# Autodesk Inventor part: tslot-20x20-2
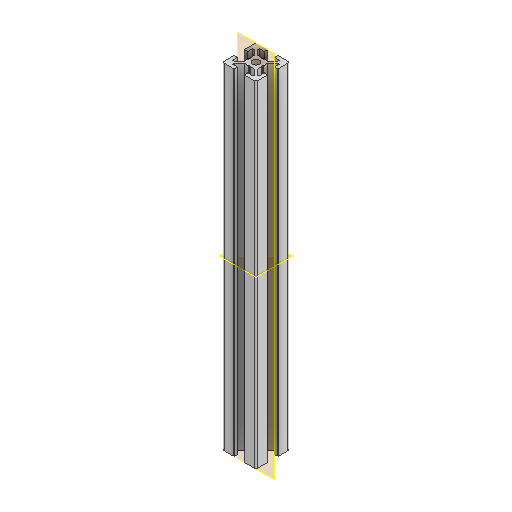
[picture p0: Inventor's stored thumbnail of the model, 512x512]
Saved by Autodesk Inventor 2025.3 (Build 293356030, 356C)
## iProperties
Created: 2025-03
Part Number: tslot-20x20-2
Material: Generico
Document SubType Name: Modeling
Designer: Ryzen5700u
Density: 1 g/cm^3
Appearance: Default
Author: Ryzen5700u
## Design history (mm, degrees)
feature "Base1"
sketch "Schizzo1"
  geometry: L1 (3.761, -16)-(4.7, -16) reference; L2 (3.761, -16)-(0.7, -12.939) reference; L3 (0.7, -12.939)-(0.7, -10.52) reference; L4 (0.4, -10)-(0.7, -10.52) reference; L5 (0.4, -10)-(0.7, -9.48) reference; L6 (0.7, -7.061)-(0.7, -9.48) reference; L7 (3.761, -4)-(0.7, -7.061) reference; L8 (3.761, -4)-(4.7, -4) reference; L9 (4.7, -4)-(4.7, -7) reference; L10 (4.7, -7)-(6.4, -7) reference; L11 (6.7, -6.7)-(6.7, -1) reference; L12 (5.7, 0)-(0, 0) reference; L13 (-0.3, -2)-(-0.3, -0.3) reference; L14 (2.7, -2)-(-0.3, -2) reference; L15 (2.7, -2.939)-(2.7, -2) reference; L16 (2.7, -2.939)-(-0.361, -6) reference; L17 (-0.361, -6)-(-2.78, -6) reference; L18 (-3.3, -6.3)-(-2.78, -6) reference; L19 (-3.3, -6.3)-(-3.82, -6) reference; L20 (-6.239, -6)-(-3.82, -6) reference; L21 (-9.3, -2.939)-(-6.239, -6) reference; L22 (-9.3, -2.939)-(-9.3, -2) reference; L23 (-9.3, -2)-(-6.3, -2) reference; L24 (-6.3, -2)-(-6.3, -0.3) reference; L25 (-12.3, 0)-(-6.6, 0) reference; L26 (-13.3, -6.7)-(-13.3, -1) reference; L27 (-11.3, -7)-(-13, -7) reference; L28 (-11.3, -4)-(-11.3, -7) reference; L29 (-10.361, -4)-(-11.3, -4) reference; L30 (-10.361, -4)-(-7.3, -7.061) reference; L31 (-7.3, -7.061)-(-7.3, -9.48) reference; L32 (-7, -10)-(-7.3, -9.48) reference; L33 (-7, -10)-(-7.3, -10.52) reference; L34 (-7.3, -12.939)-(-7.3, -10.52) reference; L35 (-10.361, -16)-(-7.3, -12.939) reference; L36 (-10.361, -16)-(-11.3, -16) reference; L37 (-11.3, -16)-(-11.3, -13) reference; L38 (-11.3, -13)-(-13, -13) reference; L39 (-13.3, -13.3)-(-13.3, -19) reference; L40 (-12.3, -20)-(-6.6, -20) reference; L41 (-6.3, -18)-(-6.3, -19.7) reference; L42 (-9.3, -18)-(-6.3, -18) reference; L43 (-9.3, -17.061)-(-9.3, -18) reference; L44 (-9.3, -17.061)-(-6.239, -14) reference; L45 (-6.239, -14)-(-3.82, -14) reference; L46 (-3.3, -13.7)-(-3.82, -14) reference; L47 (-3.3, -13.7)-(-2.78, -14) reference; L48 (-0.361, -14)-(-2.78, -14) reference; L49 (2.7, -17.061)-(-0.361, -14) reference; L50 (2.7, -17.061)-(2.7, -18) reference; L51 (2.7, -18)-(-0.3, -18) reference; L52 (-0.3, -18)-(-0.3, -19.7) reference; L53 (5.7, -20)-(0, -20) reference; L54 (6.7, -13.3)-(6.7, -19) reference; L55 (4.7, -13)-(6.4, -13) reference; L56 (4.7, -16)-(4.7, -13) reference; C1 r 2.1 at (-3.3, -10) reference; A1 r 0.3 centre (6.4, -6.7) between (6.4, -7) and (6.7, -6.7) reference; A2 r 1 centre (5.7, -1) between (6.7, -1) and (5.7, 0) reference; A3 r 0.3 centre (0, -0.3) between (0, 0) and (-0.3, -0.3) reference; A4 r 0.3 centre (-6.6, -0.3) between (-6.3, -0.3) and (-6.6, 0) reference; A5 r 1 centre (-12.3, -1) between (-12.3, 0) and (-13.3, -1) reference; A6 r 0.3 centre (-13, -6.7) between (-13.3, -6.7) and (-13, -7) reference; A7 r 0.3 centre (-13, -13.3) between (-13, -13) and (-13.3, -13.3) reference; A8 r 1 centre (-12.3, -19) between (-13.3, -19) and (-12.3, -20) reference; A9 r 0.3 centre (-6.6, -19.7) between (-6.6, -20) and (-6.3, -19.7) reference; A10 r 0.3 centre (0, -19.7) between (-0.3, -19.7) and (0, -20) reference; A11 r 1 centre (5.7, -19) between (5.7, -20) and (6.7, -19) reference; A12 r 0.3 centre (6.4, -13.3) between (6.7, -13.3) and (6.4, -13) reference; 1 further point
extrude "Estrusione1" join sketch "Schizzo1" distance "d0" = 190; taper "d1" = 0 deg
node "Piano di lavoro1"
node "Solido1"
node "Linea chiusa proiettata1"
